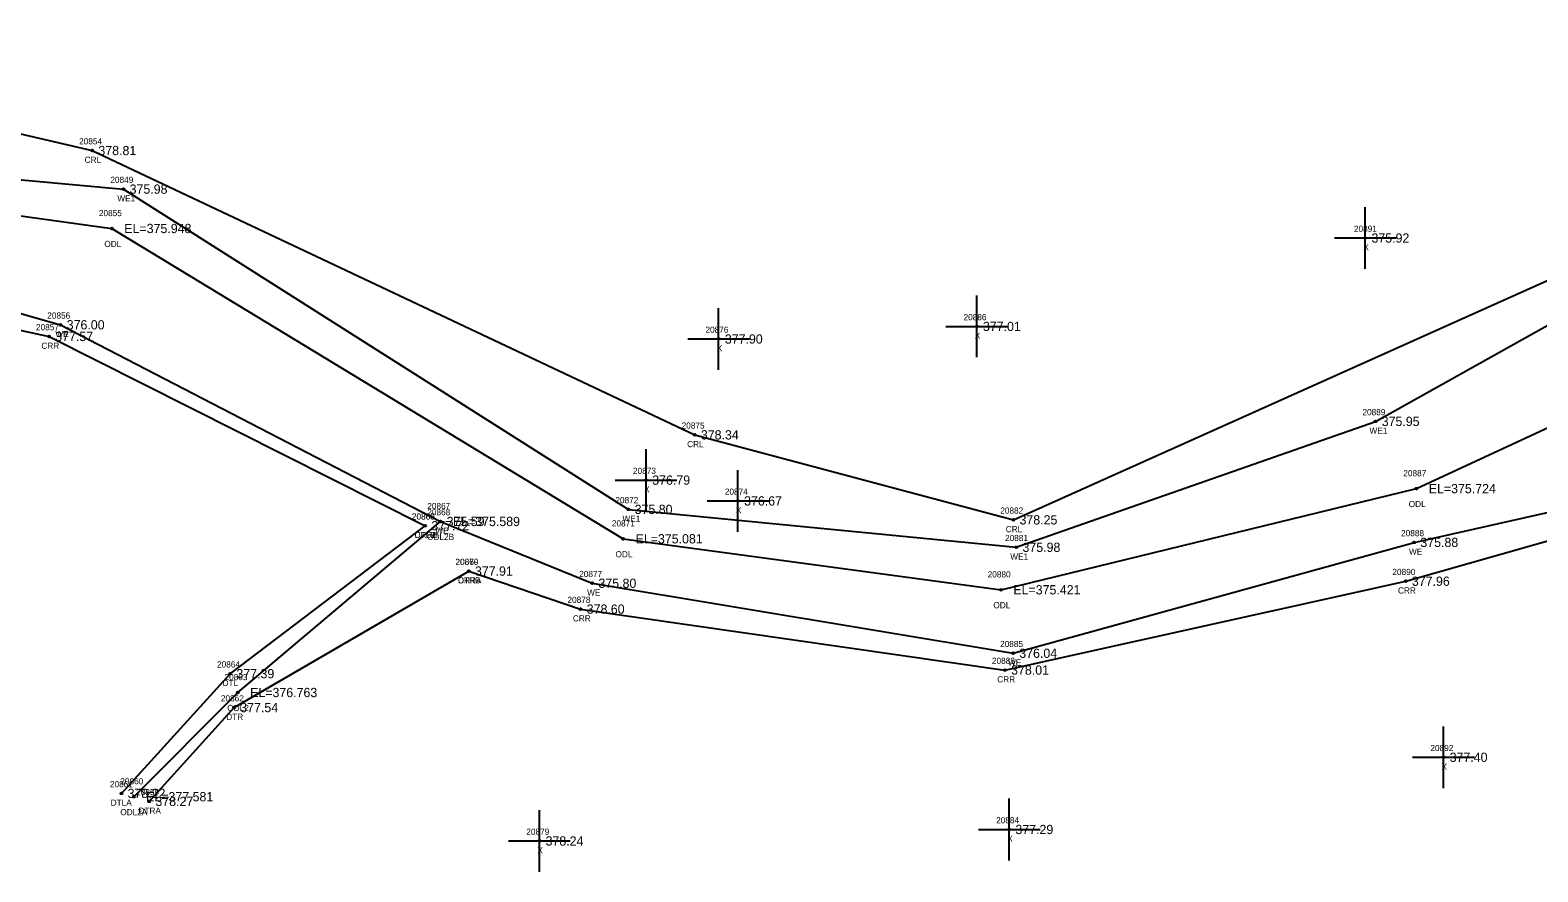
# Model space of a CAD drawing. Extents: x 2116373 to 2118139, y 979529 to 981026.
# Drawn here: x 2117487.1 to 2117731.3, y 979928.5 to 980064.9 of the extents above; entities that cross this region are included whole.
import ezdxf

# ---------------------------------------------------------------- set-up
doc = ezdxf.new("R2010")
doc.units = 0
for name, color, linetype in [('RD_EX_H2O', 7, 'Continuous'), ('RD_EX_H2O_txCode', 7, 'Continuous'), ('RD_EX_Misc', 7, 'Continuous'), ('RD_EX_Misc_txCode', 7, 'Continuous'), ('RD_EX_TX_H2O_ELEV', 7, 'Continuous'), ('RD_EX_TX_Misc_ELEV', 7, 'Continuous'), ('RD_SMD_Locator', 7, 'Continuous')]:
    doc.layers.add(name, color=color, linetype=linetype)

msp = doc.modelspace()

# ---------------------------------------------------------------- linework, layer by layer
at = {"layer": 'RD_EX_H2O'}
for points in [[(2117055.27, 980533.4), (2117084.87, 980468.5), (2117113.12, 980396.82), (2117150.26, 980360.48), (2117172.14, 980330.53), (2117167.4, 980300.56), (2117152, 980282.05), (2117153.33, 980268.31), (2117164.01, 980260.72), (2117221.6, 980247.26), (2117265.25, 980211.02), (2117324.27, 980199.15), (2117347.37, 980175.31), (2117365.85, 980182.55), (2117389.45, 980162.29), (2117399.63, 980142.01), (2117411.26, 980120.88), (2117420.42, 980068.64), (2117446.24, 980057.21), (2117497.11, 980045.39), (2117594.71, 979999.33), (2117646.33, 979985.56), (2117750.91, 980032.44), (2117805.09, 980018.87)], [(2117320.83, 980195.76), (2117348.44, 980166.4), (2117344.42, 980159.47), (2117364.05, 980141.59), (2117409.75, 980120.17), (2117416.75, 980067.62), (2117432.5, 980045.49), (2117502.17, 980039.14), (2117583.98, 979987.26), (2117646.81, 979981.12), (2117705, 980001.51), (2117745.64, 980024.24), (2117805.06, 980014.37)], [(2117253.76, 980181.57), (2117309.73, 980180.01), (2117328.75, 980169.13), (2117302.89, 980172.19), (2117303.47, 980157.54), (2117331.87, 980146.51), (2117356.54, 980132.72), (2117379.52, 980112.38), (2117402.94, 980061.78), (2117424.79, 980029.41), (2117490.12, 980015.27), (2117551.05, 979984.61)], [(2117327.56, 980176.76), (2117343.89, 980156.23), (2117361.71, 980140.22), (2117404.48, 980117.53), (2117412.59, 980065.44), (2117429.85, 980042.55), (2117500.31, 980032.76), (2117583.13, 979982.49), (2117644.33, 979974.23), (2117711.62, 979990.62), (2117746.36, 980006.72), (2117805.28, 980007.14)], [(2117334.27, 980149.08), (2117359.88, 980134.92), (2117396.25, 980116.57), (2117405.43, 980061.84), (2117428.2, 980035.31), (2117491.98, 980017.16), (2117553.53, 979985.3), (2117578.12, 979975.29), (2117646.29, 979963.95), (2117711.26, 979981.91), (2117748.87, 979990.36), (2117810.8, 979988.9)], [(2117558.11, 979977.26), (2117576.22, 979971.1), (2117644.97, 979961.23), (2117709.89, 979975.62), (2117746.21, 979985.94), (2117810.22, 979984.54)], [(2117501.84, 979941.25), (2117519.47, 979960.64), (2117551.05, 979984.61)], [(2117503.84, 979940.71), (2117520.69, 979957.59), (2117553.53, 979985.3)], [(2117506.35, 979939.95), (2117520.09, 979955.15), (2117558.11, 979977.26)]]:
    msp.add_lwpolyline(points, dxfattribs=at)
at = {"layer": 'RD_EX_Misc'}
for p, q in [((2117703.34, 980026.22), (2117703.34, 980036.22)), ((2117698.34, 980031.22), (2117708.34, 980031.22)), ((2117640.4, 980011.9), (2117640.4, 980021.9)), ((2117598.59, 980009.86), (2117598.59, 980019.86)), ((2117635.4, 980016.9), (2117645.4, 980016.9)), ((2117593.59, 980014.86), (2117603.59, 980014.86)), ((2117586.83, 979987), (2117586.83, 979997)), ((2117601.71, 979983.63), (2117601.71, 979993.63)), ((2117581.83, 979992), (2117591.83, 979992)), ((2117596.71, 979988.63), (2117606.71, 979988.63)), ((2117716.01, 979942.1), (2117716.01, 979952.1)), ((2117711.01, 979947.1), (2117721.01, 979947.1)), ((2117645.66, 979930.4), (2117645.66, 979940.4)), ((2117569.55, 979928.54), (2117569.55, 979938.54)), ((2117640.66, 979935.4), (2117650.66, 979935.4)), ((2117564.55, 979933.54), (2117574.55, 979933.54))]:
    msp.add_line(p, q, dxfattribs=at)
at = {"layer": 'RD_SMD_Locator'}
for centre in [(2117497.11, 980045.39), (2117502.17, 980039.14), (2117500.31, 980032.76), (2117703.34, 980031.22), (2117490.12, 980015.27), (2117491.98, 980017.16), (2117640.4, 980016.9), (2117598.59, 980014.86), (2117705, 980001.51), (2117594.71, 979999.33), (2117586.83, 979992), (2117711.62, 979990.62), (2117601.71, 979988.63), (2117583.98, 979987.26), (2117551.05, 979984.61), (2117551.05, 979984.61), (2117553.53, 979985.3), (2117553.53, 979985.3), (2117646.33, 979985.56), (2117583.13, 979982.49), (2117646.81, 979981.12), (2117711.26, 979981.91), (2117558.11, 979977.26), (2117558.11, 979977.26), (2117578.12, 979975.29), (2117644.33, 979974.23), (2117709.89, 979975.62), (2117576.22, 979971.1), (2117646.29, 979963.95), (2117519.47, 979960.64), (2117644.97, 979961.23), (2117520.69, 979957.59), (2117520.09, 979955.15), (2117716.01, 979947.1), (2117501.84, 979941.25), (2117503.84, 979940.71), (2117506.35, 979939.95), (2117645.66, 979935.4), (2117569.55, 979933.54)]:
    msp.add_circle(centre, 0.15, dxfattribs=at)

# ---------------------------------------------------------------- texts
at = {"layer": 'RD_EX_H2O_txCode'}
for s, p in [('20854', (2117494.99, 980046.39)), ('CRL', (2117495.88, 980043.39)), ('20849', (2117500.05, 980040.14)), ('WE1', (2117501.18, 980037.14)), ('20855', (2117498.19, 980034.76)), ('ODL', (2117499.07, 980029.76)), ('20856', (2117489.83, 980018.16)), ('20857', (2117488, 980016.27)), ('WE', (2117491.14, 980015.16)), ('CRR', (2117488.87, 980013.27)), ('20889', (2117702.88, 980002.51)), ('20875', (2117592.59, 980000.33)), ('CRL', (2117593.48, 979997.33)), ('WE1', (2117704.02, 979999.51)), ('20887', (2117709.5, 979992.62)), ('20872', (2117581.86, 979988.26)), ('ODL', (2117710.37, 979987.62)), ('20866', (2117548.89, 979985.61)), ('20865', (2117548.91, 979985.61)), ('20867', (2117551.39, 979987.3)), ('20868', (2117551.39, 979986.3)), ('WE1', (2117583, 979985.26)), ('20882', (2117644.21, 979986.56)), ('CRRB', (2117549.33, 979982.61)), ('DTLB', (2117549.34, 979982.61)), ('WE', (2117552.69, 979983.3)), ('20871', (2117581.29, 979984.49)), ('CRL', (2117645.1, 979983.56)), ('20888', (2117709.14, 979982.91)), ('ODL2B', (2117551.36, 979982.3)), ('20881', (2117644.98, 979982.12)), ('20870', (2117555.95, 979978.26)), ('20869', (2117555.97, 979978.26)), ('ODL', (2117581.88, 979979.49)), ('WE1', (2117645.83, 979979.12)), ('WE', (2117710.42, 979979.91)), ('CRRA', (2117556.37, 979975.26)), ('DTRB', (2117556.37, 979975.26)), ('20877', (2117576, 979976.29)), ('20880', (2117642.17, 979976.23)), ('20890', (2117707.73, 979976.62)), ('WE', (2117577.28, 979973.29)), ('CRR', (2117708.64, 979973.62)), ('20878', (2117574.1, 979972.1)), ('ODL', (2117643.09, 979971.23)), ('CRR', (2117574.97, 979969.1)), ('20885', (2117644.18, 979964.95)), ('20864', (2117517.33, 979961.64)), ('20883', (2117642.86, 979962.23)), ('WE', (2117645.46, 979961.95)), ('DTL', (2117518.22, 979958.64)), ('20863', (2117518.54, 979959.59)), ('CRR', (2117643.72, 979959.23)), ('20862', (2117517.95, 979956.15)), ('DTR', (2117518.82, 979953.15)), ('ODL2', (2117518.99, 979954.59)), ('20861', (2117499.98, 979942.25)), ('20860', (2117501.66, 979942.71)), ('20859', (2117504.23, 979940.95)), ('DTLA', (2117500.1, 979939.25)), ('ODL2A', (2117501.66, 979937.71)), ('DTRA', (2117504.6, 979937.95))]:
    msp.add_text(s, height=1, dxfattribs=at).set_placement(p)
at = {"layer": 'RD_EX_Misc_txCode'}
for s, p in [('20891', (2117701.5, 980032.22)), ('X', (2117703.02, 980029.22)), ('20886', (2117638.26, 980017.9)), ('20876', (2117596.45, 980015.86)), ('X', (2117640.08, 980014.9)), ('X', (2117598.28, 980012.86)), ('20873', (2117584.71, 979993)), ('X', (2117586.52, 979990)), ('20874', (2117599.59, 979989.63)), ('X', (2117601.39, 979986.63)), ('20892', (2117713.89, 979948.1)), ('X', (2117715.69, 979945.1)), ('20884', (2117643.54, 979936.4)), ('20879', (2117567.43, 979934.54)), ('X', (2117569.23, 979931.54)), ('X', (2117645.35, 979933.4))]:
    msp.add_text(s, height=1, dxfattribs=at).set_placement(p)
at = {"layer": 'RD_EX_TX_H2O_ELEV'}
for s, p in [('378.81', (2117498.11, 980044.64)), ('375.98', (2117503.17, 980038.39)), ('EL=375.948', (2117502.31, 980032.01)), ('376.00', (2117492.98, 980016.41)), ('377.57', (2117491.12, 980014.52)), ('375.95', (2117706, 980000.76)), ('378.34', (2117595.71, 979998.58)), ('EL=375.724', (2117713.62, 979989.87)), ('375.59', (2117554.53, 979984.55)), ('EL=375.589', (2117555.53, 979984.55)), ('375.80', (2117584.98, 979986.51)), ('378.25', (2117647.33, 979984.81)), ('377.72', (2117552.05, 979983.86)), ('377.72', (2117552.05, 979983.86)), ('EL=375.081', (2117585.13, 979981.74)), ('375.98', (2117647.81, 979980.37)), ('375.88', (2117712.26, 979981.16)), ('377.91', (2117559.11, 979976.51)), ('377.91', (2117559.11, 979976.51)), ('377.96', (2117710.89, 979974.87)), ('375.80', (2117579.12, 979974.54)), ('EL=375.421', (2117646.33, 979973.48)), ('378.60', (2117577.22, 979970.35)), ('376.04', (2117647.29, 979963.2)), ('378.01', (2117645.97, 979960.48)), ('377.39', (2117520.47, 979959.89)), ('EL=376.763', (2117522.69, 979956.84)), ('377.54', (2117521.09, 979954.4)), ('378.22', (2117502.84, 979940.5)), ('EL=377.581', (2117505.84, 979939.96)), ('378.27', (2117507.35, 979939.2))]:
    msp.add_text(s, height=1.5, dxfattribs=at).set_placement(p)
at = {"layer": 'RD_EX_TX_Misc_ELEV'}
for s, p in [('375.92', (2117704.34, 980030.47)), ('377.01', (2117641.4, 980016.15)), ('377.90', (2117599.59, 980014.11)), ('376.79', (2117587.83, 979991.25)), ('376.67', (2117602.71, 979987.88)), ('377.40', (2117717.01, 979946.35)), ('377.29', (2117646.66, 979934.65)), ('378.24', (2117570.55, 979932.79))]:
    msp.add_text(s, height=1.5, dxfattribs=at).set_placement(p)

doc.saveas('drawing.dxf')
